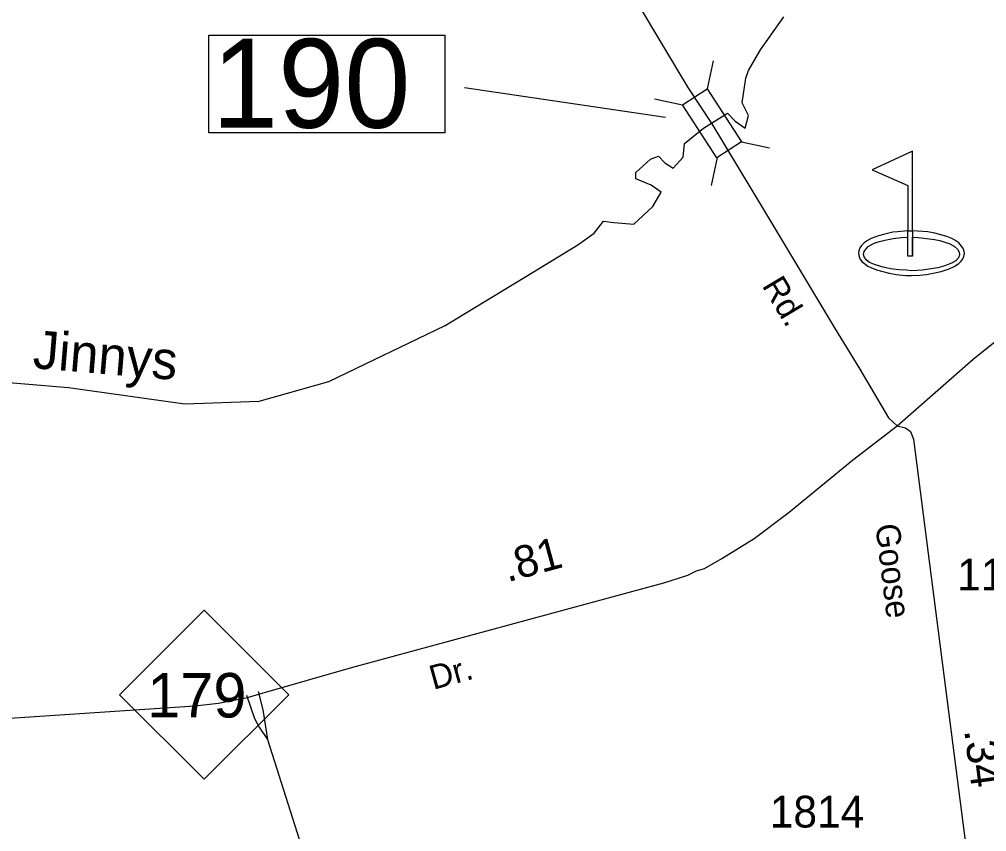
# Model space of a CAD drawing. Extents: x 2104537 to 2336408, y 34176 to 229611.
# Drawn here: x 2174421 to 2178229, y 59254 to 62451 of the extents above; entities that cross this region are included whole.
import ezdxf

# ---------------------------------------------------------------- set-up
doc = ezdxf.new("R2010")
doc.units = 0
for name, color, linetype in [('Exist Cultural Recreational Golf Course CELL', 7, 'Continuous'), ('Exist Hydrographic Creek Single Shore', 7, 'Continuous'), ('Exist Road Non-System Type 51', 7, 'Continuous'), ('Exist Road Primary NC Attributed', 7, 'Continuous'), ('Exist Road Primary NC Label', 7, 'Continuous'), ('Exist Road Primary NC Mileage Hundredths English Label', 7, 'Continuous'), ('Exist Road Primary NC Shield CELL', 7, 'Continuous'), ('Exist Road Primary NC Shield Number Label', 7, 'Continuous'), ('Exist Road Secondary Mileage Hundredths English Label', 7, 'Continuous'), ('Exist Road Secondary Structure Standard Bridge CELL', 7, 'Continuous'), ('Exist Road Secondary Structure Standard Bridge Number Label', 7, 'Continuous'), ('Exist Road Secondary Type 51 Attributed', 7, 'Continuous'), ('Exist Road Secondary Type 51 Label', 7, 'Continuous'), ('Exist Road Secondary Type 51 Number Label', 7, 'Continuous'), ('Old_Level_32', 7, 'Continuous')]:
    doc.layers.add(name, color=color, linetype=linetype)

msp = doc.modelspace()

# ---------------------------------------------------------------- linework, layer by layer
at = {"layer": 'Exist Cultural Recreational Golf Course CELL'}
msp.add_lwpolyline([(2177937.8, 61932.4), (2177779.3, 61859), (2177919.3, 61797.4), (2177919.3, 61618.6), (2177937.8, 61618.6), (2177937.8, 61593.5), (2177937.8, 61518.5), (2177937.8, 61593.5), (2177961.4, 61592), (2177991.9, 61588.7), (2178023.5, 61584.7), (2178044.6, 61580.4), (2178072.5, 61572.1), (2178079.4, 61569.9), (2178102.1, 61558.2), (2178114.1, 61547.2), (2178119.6, 61537.6), (2178122.6, 61528.1), (2178122.3, 61523.8), (2178121.3, 61519.6), (2178120.3, 61516.3), (2178118.1, 61512.6), (2178107.4, 61500.7), (2178091.6, 61491.2), (2178064.3, 61480.8), (2178037.7, 61473.3), (2178002.2, 61467.8), (2177975.2, 61463.8), (2177935, 61461.9), (2177912.6, 61463.8), (2177883.5, 61465.3), (2177850.5, 61469.8), (2177816.4, 61477.3), (2177787.4, 61485.8), (2177767.9, 61494.3), (2177755.9, 61503.8), (2177747.4, 61515.9), (2177744.9, 61525.9), (2177747.4, 61536.9), (2177754.4, 61547.9), (2177762.9, 61557.4), (2177772, 61562.7), (2177783.4, 61568.4), (2177802.5, 61575), (2177828.7, 61581.9), (2177861.5, 61588), (2177893.6, 61592), (2177919.3, 61593.5), (2177919.3, 61618.6), (2177937.8, 61618.6), (2177937.8, 61518.5), (2177919.3, 61518.5), (2177919.3, 61593.5), (2177919.3, 61618.6), (2177878.9, 61614.9), (2177859.4, 61613.1), (2177828.6, 61605.9), (2177803.1, 61599.6), (2177774.8, 61588.6), (2177762.4, 61581.4), (2177746.6, 61571.7), (2177736.3, 61560.7), (2177730.1, 61552.4), (2177726.1, 61540.1), (2177725.1, 61530.4), (2177727.8, 61515.9), (2177730.6, 61508.8), (2177739.6, 61496.6), (2177747.9, 61489.6), (2177761.8, 61479.9), (2177773.5, 61474.2), (2177796, 61464.7), (2177814.8, 61459.7), (2177845.1, 61452.4), (2177873.1, 61446.9), (2177909.6, 61443.5), (2177933.1, 61442.5), (2177966.9, 61444.5), (2177992.2, 61447), (2178018.6, 61451.6), (2178050.6, 61458.2), (2178081.7, 61468.7), (2178101.1, 61478.6), (2178119.6, 61489.8), (2178129.4, 61499.8), (2178135.4, 61508.1), (2178138, 61513.6), (2178139.4, 61517.7), (2178140.8, 61524.1), (2178141.6, 61530.9), (2178140.1, 61542.1), (2178135.6, 61552.4), (2178125.7, 61565), (2178119.5, 61571.8), (2178104.7, 61581.6), (2178092.9, 61588.3), (2178072.2, 61596.8), (2178057.9, 61600.8), (2178024.8, 61609.6), (2177997.3, 61614.6), (2177937.8, 61618.6)], close=True, dxfattribs=at)
at = {"layer": 'Exist Hydrographic Creek Single Shore'}
msp.add_lwpolyline([(2173848.4, 61066.4), (2174615.5, 61002.4), (2175073.4, 60937.8), (2175365.4, 60948.6), (2175640.3, 61025.3), (2176097.4, 61246.1), (2176410.9, 61436.8), (2176620.5, 61564.2), (2176684.5, 61609.5), (2176720.6, 61656.7), (2176762.2, 61651.1), (2176839.8, 61645.6), (2176914.7, 61715), (2176948, 61770.5), (2176909.2, 61798.2), (2176848.2, 61823.2), (2176848.2, 61848.2), (2176906.4, 61900.9), (2176936.9, 61912), (2176961.9, 61887), (2176995.2, 61864.8), (2177034, 61909.2), (2177039.5, 61962), (2177114.4, 62023), (2177208.7, 62081.3), (2177239.2, 62050.8), (2177278.1, 62023), (2177291.9, 62073), (2177267, 62122.9), (2177280.8, 62220.1), (2177291.4, 62250.1), (2177339.1, 62331.1), (2177431.5, 62460.6)], dxfattribs=at)
at = {"layer": 'Exist Road Non-System Type 51'}
msp.add_line((2175398.7, 59616.1), (2175551.5, 59134.9), dxfattribs=at)
for points in [[(2175315.8, 59791), (2175347.8, 59698.8), (2175365.9, 59665), (2175398.7, 59616.1)], [(2175361.4, 59806.2), (2175380, 59733), (2175398.7, 59616.1)]]:
    msp.add_lwpolyline(points, dxfattribs=at)
at = {"layer": 'Exist Road Primary NC Attributed'}
for points in [[(2177876.5, 60850.7), (2178175.8, 61114.2), (2178381.1, 61278), (2178534.4, 61381.7), (2178652.3, 61440.9), (2178750.3, 61488.6), (2178904, 61546.6), (2179053.9, 61594.6), (2179489.3, 61700.4), (2179545.1, 61716.7), (2179624.3, 61741.4), (2179650.9, 61758), (2179669.3, 61780.6), (2179680.9, 61802)], [(2173866.7, 59588.4), (2173957.6, 59627.9), (2174033.2, 59647.7), (2174177.5, 59679.1), (2174223.5, 59685.4), (2174343.5, 59697.8), (2175112.3, 59749), (2175206, 59759), (2175319.3, 59781.8), (2175378, 59798.9), (2175734.6, 59901), (2176818.1, 60195.3), (2176958.9, 60233.4), (2177052.7, 60263.7), (2177086.8, 60280.1), (2177118.8, 60290), (2177186.8, 60328.7), (2177314.3, 60407.3), (2177451.5, 60511.9), (2177700.6, 60715.5), (2177876.5, 60850.7)]]:
    msp.add_lwpolyline(points, dxfattribs=at)
at = {"layer": 'Exist Road Primary NC Shield CELL'}
msp.add_lwpolyline([(2174815.8, 59793), (2175148.8, 60126), (2175481.8, 59793), (2175148.8, 59460)], close=True, dxfattribs=at)
at = {"layer": 'Exist Road Secondary Structure Standard Bridge CELL'}
for p, q in [((2177153.1, 62288.1), (2177129.5, 62177.4)), ((2176921.6, 62138), (2177032.3, 62114.4)), ((2177263.9, 61969.1), (2177374.6, 61945.5)), ((2177168.9, 61907.5), (2177145.3, 61796.8))]:
    msp.add_line(p, q, dxfattribs=at)
msp.add_lwpolyline([(2177129.5, 62177.4), (2177264.3, 61969.4), (2177167.2, 61906.4), (2177032.3, 62114.4)], close=True, dxfattribs=at)
at = {"layer": 'Exist Road Secondary Structure Standard Bridge Number Label'}
msp.add_line((2176965.3, 62064.9), (2176174.1, 62182.1), dxfattribs=at)
msp.add_lwpolyline([(2175167.4, 62388.8), (2176096.4, 62388.8), (2176096.4, 62004.7), (2175167.4, 62004.7)], close=True, dxfattribs=at)
at = {"layer": 'Exist Road Secondary Type 51 Attributed'}
for points in [[(2175994.4, 64175.7), (2176021.7, 64135.7), (2176058.8, 64075.7), (2176144.6, 63889.7), (2176239.2, 63688.4), (2176383.7, 63373.5), (2176506, 63132.7), (2176540.6, 63064.8), (2176853.4, 62516), (2177052.9, 62183.4), (2177148, 62040)], [(2177148, 62040), (2177355.3, 61696.2), (2177629.9, 61236.9), (2177730.7, 61073.8), (2177843.1, 60882.6), (2177876.5, 60850.7)], [(2177876.5, 60850.7), (2177909.7, 60843.8), (2177930.2, 60828.4), (2177941.7, 60799), (2177999.4, 60348.1), (2178102, 59553.1), (2178157.9, 59116)]]:
    msp.add_lwpolyline(points, dxfattribs=at)

# ---------------------------------------------------------------- texts
at = {"layer": 'Exist Road Primary NC Label'}
msp.add_text('Dr.', height=95, rotation=15.4492, dxfattribs=at).set_placement((2176051.3, 59811.8))
at = {"layer": 'Exist Road Primary NC Mileage Hundredths English Label'}
msp.add_text('.81', height=125, rotation=15.1946, dxfattribs=at).set_placement((2176343.1, 60235.4))
at = {"layer": 'Exist Road Primary NC Shield Number Label'}
msp.add_text('179', height=175, dxfattribs=at).set_placement((2174924.9, 59703.3))
at = {"layer": 'Exist Road Secondary Mileage Hundredths English Label'}
msp.add_text('.34', height=125, rotation=277.3535, dxfattribs=at).set_placement((2178140.6, 59652.6))
at = {"layer": 'Exist Road Secondary Structure Standard Bridge Number Label'}
msp.add_text('190', height=350, dxfattribs=at).set_placement((2175180, 62024.5))
at = {"layer": 'Exist Road Secondary Type 51 Label'}
for s, rotation, p in [('Rd.', 300.8724, (2177343, 61403)), ('Goose', 277.0022, (2177791, 60460.7))]:
    msp.add_text(s, height=95, rotation=rotation, dxfattribs=at).set_placement(p)
at = {"layer": 'Exist Road Secondary Type 51 Number Label'}
for s, p in [('1155', (2178113.2, 60203.2)), ('1814', (2177375.6, 59270.2))]:
    msp.add_text(s, height=125, dxfattribs=at).set_placement(p)
at = {"layer": 'Old_Level_32'}
msp.add_text('Jinnys', height=150, rotation=355.2302, dxfattribs=at).set_placement((2174471.6, 61078.7))

doc.saveas('drawing.dxf')
